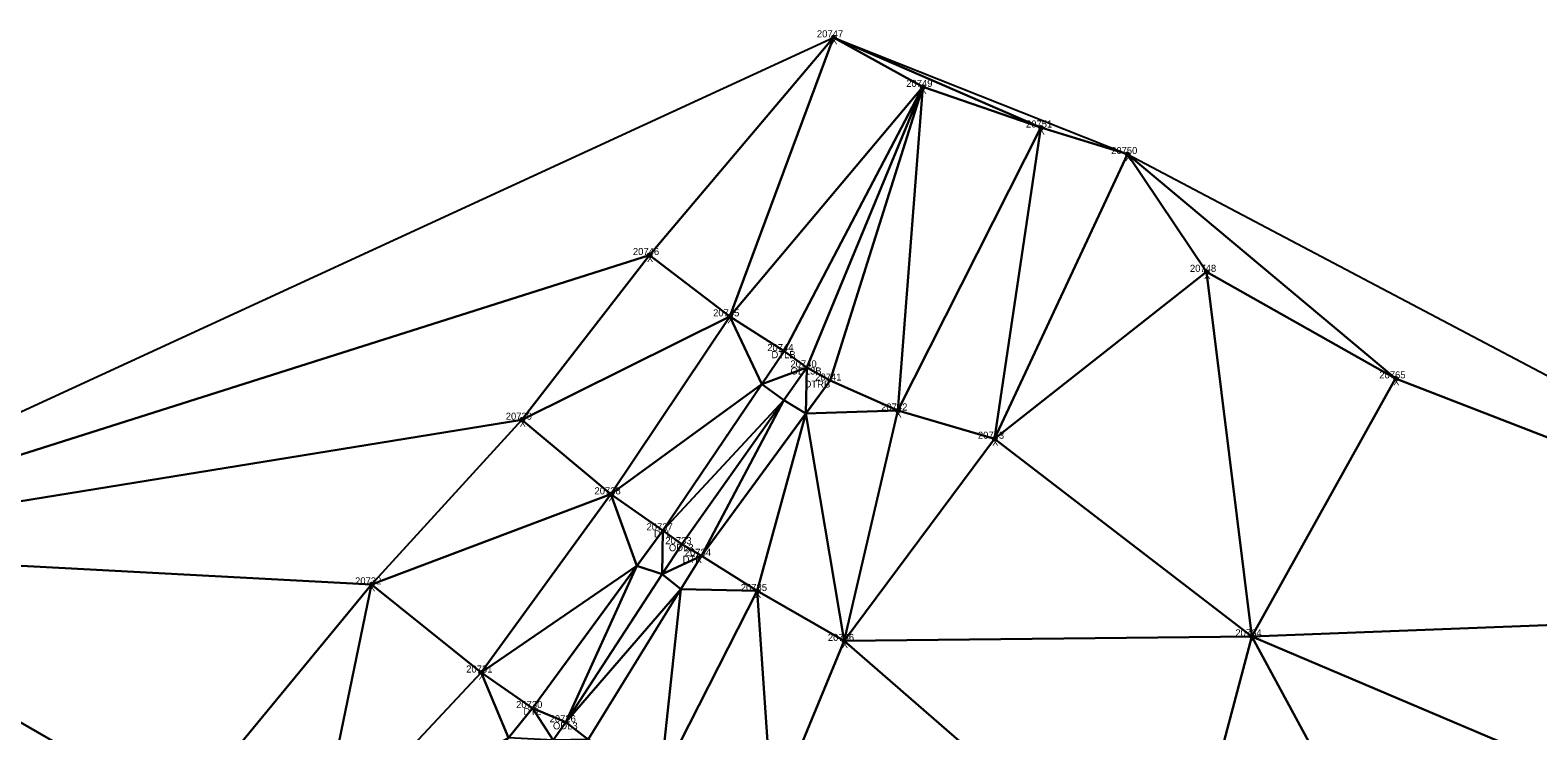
# Model space of a CAD drawing. Extents: x 1966740 to 1969291, y 1117379 to 1118460.
# Drawn here: x 1968833.8 to 1969047.3, y 1117968.4 to 1118067.6 of the extents above; entities that cross this region are included whole.
import ezdxf

# ---------------------------------------------------------------- set-up
doc = ezdxf.new("R2010")
doc.units = 0
for name, color, linetype in [('Level 10', 7, 'Continuous'), ('Level 30', 7, 'Continuous'), ('Level 35', 7, 'Continuous'), ('Level 50', 7, 'Continuous'), ('Level 52', 7, 'Continuous'), ('Level 53', 7, 'Continuous'), ('Level 6', 7, 'Continuous'), ('Level 60', 7, 'Continuous'), ('Level 61', 7, 'Continuous'), ('Level 62', 7, 'Continuous')]:
    doc.layers.add(name, color=color, linetype=linetype)

msp = doc.modelspace()

# ---------------------------------------------------------------- linework, layer by layer
at = {"layer": 'Level 10'}
for points in [[(1968872.44, 1117926.13), (1968885.78, 1117948), (1968904.93, 1117971.61), (1968923.41, 1117996.78), (1968940.56, 1118022.16)], [(1968882.13, 1117923.29), (1968896.84, 1117943.36), (1968912.83, 1117967.16), (1968928.85, 1117993.17), (1968947.1, 1118017.99)]]:
    msp.add_lwpolyline(points, dxfattribs=at)
at = {"layer": 'Level 30'}
for centre in [(1968947.56, 1118066.6), (1968960.19, 1118059.58), (1968976.93, 1118053.83), (1968989.19, 1118050.07), (1968921.48, 1118035.77), (1969000.39, 1118033.39), (1968932.86, 1118027.08), (1969027.17, 1118018.3), (1968956.66, 1118013.75), (1968903.44, 1118012.44), (1968970.36, 1118009.75), (1968916.03, 1118001.88), (1968882.12, 1117989.12), (1968936.75, 1117988.2), (1969006.8, 1117981.76), (1968949.07, 1117981.12), (1968897.65, 1117976.64)]:
    msp.add_circle(centre, 0.25, dxfattribs=at)
at = {"layer": 'Level 35'}
for points in [[(1968789.99, 1117994), (1968947.56, 1118066.6), (1968921.48, 1118035.77)], [(1968921.48, 1118035.77), (1968947.56, 1118066.6), (1968932.86, 1118027.08)], [(1968932.86, 1118027.08), (1968947.56, 1118066.6), (1968960.19, 1118059.58)], [(1968947.56, 1118066.6), (1968989.19, 1118050.07), (1968976.93, 1118053.83)], [(1968947.56, 1118066.6), (1968976.93, 1118053.83), (1968960.19, 1118059.58)], [(1968932.86, 1118027.08), (1968960.19, 1118059.58), (1968940.56, 1118022.16)], [(1968940.56, 1118022.16), (1968960.19, 1118059.58), (1968943.8, 1118019.85)], [(1968943.8, 1118019.85), (1968960.19, 1118059.58), (1968947.1, 1118017.99)], [(1968947.1, 1118017.99), (1968960.19, 1118059.58), (1968956.66, 1118013.75)], [(1968956.66, 1118013.75), (1968960.19, 1118059.58), (1968976.93, 1118053.83)], [(1968956.66, 1118013.75), (1968976.93, 1118053.83), (1968970.36, 1118009.75)], [(1968970.36, 1118009.75), (1968976.93, 1118053.83), (1968989.19, 1118050.07)], [(1968970.36, 1118009.75), (1968989.19, 1118050.07), (1969000.39, 1118033.39)], [(1968989.19, 1118050.07), (1969111.1, 1117985.78), (1969027.17, 1118018.3)], [(1968989.19, 1118050.07), (1969027.17, 1118018.3), (1969000.39, 1118033.39)], [(1968789.99, 1117994), (1968921.48, 1118035.77), (1968903.44, 1118012.44)], [(1968903.44, 1118012.44), (1968921.48, 1118035.77), (1968932.86, 1118027.08)], [(1968970.36, 1118009.75), (1969000.39, 1118033.39), (1969006.8, 1117981.76)], [(1969000.39, 1118033.39), (1969027.17, 1118018.3), (1969006.8, 1117981.76)], [(1968903.44, 1118012.44), (1968932.86, 1118027.08), (1968916.03, 1118001.88)], [(1968916.03, 1118001.88), (1968932.86, 1118027.08), (1968937.41, 1118017.5)], [(1968932.86, 1118027.08), (1968940.56, 1118022.16), (1968937.41, 1118017.5)], [(1968937.41, 1118017.5), (1968940.56, 1118022.16), (1968943.8, 1118019.85)], [(1968937.41, 1118017.5), (1968943.8, 1118019.85), (1968940.52, 1118015.22)], [(1968940.52, 1118015.22), (1968943.8, 1118019.85), (1968943.66, 1118013.31)], [(1968943.66, 1118013.31), (1968943.8, 1118019.85), (1968947.1, 1118017.99)], [(1969006.8, 1117981.76), (1969027.17, 1118018.3), (1969111.1, 1117985.78)], [(1968916.03, 1118001.88), (1968937.41, 1118017.5), (1968923.41, 1117996.78)], [(1968923.41, 1117996.78), (1968937.41, 1118017.5), (1968940.52, 1118015.22)], [(1968943.66, 1118013.31), (1968947.1, 1118017.99), (1968956.66, 1118013.75)], [(1968923.41, 1117996.78), (1968940.52, 1118015.22), (1968926.07, 1117994.82)], [(1968926.07, 1117994.82), (1968940.52, 1118015.22), (1968928.85, 1117993.17)], [(1968928.85, 1117993.17), (1968940.52, 1118015.22), (1968943.66, 1118013.31)], [(1968789.99, 1117994), (1968903.44, 1118012.44), (1968882.12, 1117989.12)], [(1968882.12, 1117989.12), (1968903.44, 1118012.44), (1968916.03, 1118001.88)], [(1968928.85, 1117993.17), (1968943.66, 1118013.31), (1968936.75, 1117988.2)], [(1968936.75, 1117988.2), (1968943.66, 1118013.31), (1968949.07, 1117981.12)], [(1968943.66, 1118013.31), (1968956.66, 1118013.75), (1968949.07, 1117981.12)], [(1968949.07, 1117981.12), (1968956.66, 1118013.75), (1968970.36, 1118009.75)], [(1968949.07, 1117981.12), (1968970.36, 1118009.75), (1969006.8, 1117981.76)], [(1968882.12, 1117989.12), (1968916.03, 1118001.88), (1968897.65, 1117976.64)], [(1968897.65, 1117976.64), (1968916.03, 1118001.88), (1968919.72, 1117991.76)], [(1968916.03, 1118001.88), (1968923.41, 1117996.78), (1968919.72, 1117991.76)], [(1968919.72, 1117991.76), (1968923.41, 1117996.78), (1968923.29, 1117990.55)], [(1968923.29, 1117990.55), (1968923.41, 1117996.78), (1968926.07, 1117994.82)], [(1968923.29, 1117990.55), (1968926.07, 1117994.82), (1968928.85, 1117993.17)], [(1968785.82, 1117960.59), (1968789.99, 1117994), (1968855.24, 1117956.42)], [(1968789.99, 1117994), (1968882.12, 1117989.12), (1968855.24, 1117956.42)], [(1968923.29, 1117990.55), (1968928.85, 1117993.17), (1968925.94, 1117988.45)], [(1968925.94, 1117988.45), (1968928.85, 1117993.17), (1968936.75, 1117988.2)], [(1968897.65, 1117976.64), (1968919.72, 1117991.76), (1968904.93, 1117971.61)], [(1968904.93, 1117971.61), (1968919.72, 1117991.76), (1968909.65, 1117969.6)], [(1968909.65, 1117969.6), (1968919.72, 1117991.76), (1968923.29, 1117990.55)], [(1968909.65, 1117969.6), (1968923.29, 1117990.55), (1968925.94, 1117988.45)], [(1968855.24, 1117956.42), (1968882.12, 1117989.12), (1968874.43, 1117951.83)], [(1968874.43, 1117951.83), (1968882.12, 1117989.12), (1968897.65, 1117976.64)], [(1968909.65, 1117969.6), (1968925.94, 1117988.45), (1968912.83, 1117967.16)], [(1968912.83, 1117967.16), (1968925.94, 1117988.45), (1968923.03, 1117961.23)], [(1968923.03, 1117961.23), (1968925.94, 1117988.45), (1968936.75, 1117988.2)], [(1968923.03, 1117961.23), (1968936.75, 1117988.2), (1968938.93, 1117956.53)], [(1968936.75, 1117988.2), (1968949.07, 1117981.12), (1968938.93, 1117956.53)], [(1969006.8, 1117981.76), (1969111.1, 1117985.78), (1969100.72, 1117941.88)], [(1968938.93, 1117956.53), (1968949.07, 1117981.12), (1968995.87, 1117940.46)], [(1968949.07, 1117981.12), (1969006.8, 1117981.76), (1968995.87, 1117940.46)], [(1968995.87, 1117940.46), (1969006.8, 1117981.76), (1969041.66, 1117917.33)], [(1969006.8, 1117981.76), (1969100.72, 1117941.88), (1969041.66, 1117917.33)], [(1968874.43, 1117951.83), (1968897.65, 1117976.64), (1968901.53, 1117967.41)], [(1968897.65, 1117976.64), (1968904.93, 1117971.61), (1968901.53, 1117967.41)], [(1968901.53, 1117967.41), (1968904.93, 1117971.61), (1968907.84, 1117967.04)], [(1968904.93, 1117971.61), (1968909.65, 1117969.6), (1968907.84, 1117967.04)], [(1968907.84, 1117967.04), (1968909.65, 1117969.6), (1968912.83, 1117967.16)]]:
    msp.add_lwpolyline(points, close=True, dxfattribs=at)
at = {"layer": 'Level 50'}
for centre in [(1968940.56, 1118022.16), (1968943.8, 1118019.85), (1968947.1, 1118017.99), (1968923.41, 1117996.78), (1968926.07, 1117994.82), (1968928.85, 1117993.17), (1968904.93, 1117971.61), (1968909.65, 1117969.6)]:
    msp.add_circle(centre, 0.001, dxfattribs=at)
at = {"layer": 'Level 6'}
msp.add_lwpolyline([(1968871.74, 1117920.38), (1968873.64, 1117922.68), (1968893.41, 1117946.64), (1968909.65, 1117969.6), (1968926.07, 1117994.82), (1968943.8, 1118019.85)], dxfattribs=at)

# ---------------------------------------------------------------- texts
at = {"layer": 'Level 52'}
for s, p in [('20747', (1968945.21, 1118066.6)), ('20749', (1968957.86, 1118059.58)), ('20751', (1968974.82, 1118053.83)), ('20750', (1968986.87, 1118050.07)), ('20746', (1968919.15, 1118035.77)), ('20748', (1968998.04, 1118033.39)), ('20745', (1968930.51, 1118027.08)), ('ODL3B', (1968941.49, 1118018.85)), ('20765', (1969024.86, 1118018.3)), ('20742', (1968954.31, 1118013.75)), ('20739', (1968901.14, 1118012.44)), ('20743', (1968968.01, 1118009.75)), ('20738', (1968913.71, 1118001.88)), ('ODL3', (1968924.25, 1117993.82)), ('20732', (1968879.8, 1117989.12)), ('20735', (1968934.43, 1117988.2)), ('20736', (1968946.76, 1117981.12)), ('20764', (1969004.47, 1117981.76)), ('20731', (1968895.54, 1117976.64)), ('ODL3', (1968907.83, 1117968.6))]:
    msp.add_text(s, height=1, dxfattribs=at).set_placement(p)
at = {"layer": 'Level 53'}
for s, p in [('20740', (1968941.46, 1118019.85)), ('20733', (1968923.74, 1117994.82)), ('20726', (1968907.35, 1117969.6))]:
    msp.add_text(s, height=1, dxfattribs=at).set_placement(p)
at = {"layer": 'Level 60'}
for s, p in [('DTLB', (1968938.78, 1118021.16)), ('DTRB', (1968943.46, 1118016.99)), ('DTL', (1968922.13, 1117995.78)), ('DTR', (1968926.19, 1117992.17)), ('DTL', (1968903.65, 1117970.61))]:
    msp.add_text(s, height=1, dxfattribs=at).set_placement(p)
at = {"layer": 'Level 61'}
for s, p in [('20744', (1968938.18, 1118022.16)), ('20741', (1968944.97, 1118017.99)), ('20737', (1968921.08, 1117996.78)), ('20734', (1968926.5, 1117993.17)), ('20730', (1968902.61, 1117971.61))]:
    msp.add_text(s, height=1, dxfattribs=at).set_placement(p)
at = {"layer": 'Level 62'}
for p in [(1968947.23, 1118065.6), (1968959.86, 1118058.58), (1968976.6, 1118052.83), (1968988.86, 1118049.07), (1968921.14, 1118034.77), (1969000.05, 1118032.39), (1968932.52, 1118026.08), (1969026.83, 1118017.3), (1968903.1, 1118011.44), (1968956.33, 1118012.75), (1968970.03, 1118008.75), (1968915.7, 1118000.88), (1968881.79, 1117988.12), (1968936.42, 1117987.2), (1968948.73, 1117980.12), (1969006.46, 1117980.76), (1968897.31, 1117975.64)]:
    msp.add_text('X', height=1, dxfattribs=at).set_placement(p)

doc.saveas('drawing.dxf')
